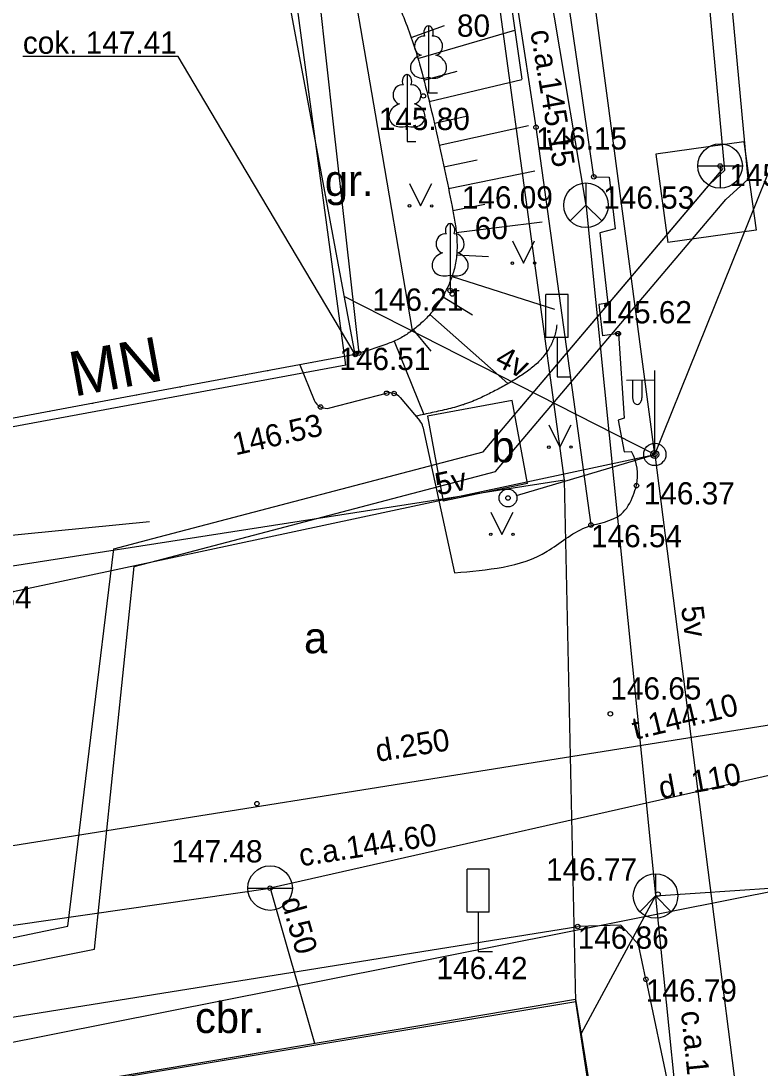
# Model space of a CAD drawing. Extents: x 728492 to 729038, y 272968 to 273171.
# Drawn here: x 728651.84 to 728668.45, y 273065.2 to 273088.71 of the extents above; entities that cross this region are included whole.
import ezdxf

# ---------------------------------------------------------------- set-up
doc = ezdxf.new("R2010")
doc.units = 0
for name, color, linetype in [('APGR_SARK_####_####_#', 7, 'Continuous'), ('APGS_ELEM_####_####_#', 7, 'Continuous'), ('BUVE_BDET_####_####_#', 7, 'Continuous'), ('BUVE_BDET_####_TKST_#', 7, 'Continuous'), ('BUVE_EKAS_####_####_#', 7, 'Continuous'), ('BUVE_EKAS_RAKS_TKST_#', 7, 'Continuous'), ('CELI_CAPM_####_####_#', 7, 'Continuous'), ('CELI_CMAL_####_####_#', 7, 'Continuous'), ('CELI_CSEG_####_TKST_#', 7, 'Continuous'), ('CELI_ELEM_####_####_#', 7, 'Continuous'), ('ELEK_ELEM_####_####_#', 7, 'Continuous'), ('ELEK_STUT_####_####_#', 7, 'Continuous'), ('ELEK_VADP_ZSPR_####_#', 7, 'Continuous'), ('ELEK_VADV_ZSPR_####_#', 7, 'Continuous'), ('ELEK_VADV_ZSPR_TKST_#', 7, 'Continuous'), ('Level 18', 7, 'Continuous'), ('RELJ_AATZ_####_TKST_#', 7, 'Continuous'), ('RELJ_ELEM_####_####_#', 7, 'Continuous'), ('RELJ_NOGA_####_####_#', 7, 'Continuous'), ('RELJ_NOGL_####_####_#', 7, 'Continuous'), ('ROBZ_UZMR_####_####_#', 7, 'Continuous'), ('SAKK_ELEM_####_####_#', 7, 'Continuous'), ('SAKK_ELEM_####_TKST_#', 7, 'Continuous'), ('SAKK_KKAN_####_####_#', 7, 'Continuous'), ('SAKK_KKAN_####_TKST_#', 7, 'Continuous'), ('SAKT_VADV_PKAB_####_#', 7, 'Continuous'), ('SILT_ELEM_####_####_#', 7, 'Continuous'), ('SILT_ELEM_####_TKST_#', 7, 'Continuous'), ('SILT_VADP_UDEN_####_#', 7, 'Continuous'), ('SILT_VADP_UDEN_TKAM_#', 7, 'Continuous'), ('SKAN_VADP_PAST_####_#', 7, 'Continuous'), ('SKAN_VADP_PAST_TKST_#', 7, 'Continuous'), ('TERT_DIAM_####_TKST_#', 7, 'Continuous'), ('TERT_ELEM_####_####_#', 7, 'Continuous'), ('UDTK_ELEM_####_####_#', 7, 'Continuous'), ('UDTK_ELEM_####_TKST_#', 7, 'Continuous'), ('UDTK_VADP_UDEN_####_#', 7, 'Continuous'), ('UDTK_VADP_UDEN_TKST_#', 7, 'Continuous')]:
    doc.layers.add(name, color=color, linetype=linetype)

msp = doc.modelspace()

# ---------------------------------------------------------------- linework, layer by layer
at = {"layer": 'APGR_SARK_####_####_#'}
for points in [[(728659.143, 273080.982), (728656.032, 273103.923)], [(728659.143, 273080.982), (728541.407, 273059.185)]]:
    msp.add_lwpolyline(points, dxfattribs=at)
at = {"layer": 'APGS_ELEM_####_####_#'}
for p, q in [((728666.081, 273080.646), (728665.446, 273080.641)), ((728665.581, 273080.642), (728665.581, 273080.25)), ((728665.791, 273080.644), (728665.791, 273080.25)), ((728666.081, 273078.979), (728666.081, 273080.862))]:
    msp.add_line(p, q, dxfattribs=at)
msp.add_circle((728666.081, 273078.979), 0.09, dxfattribs=at)
msp.add_ellipse((728665.686, 273080.25), major_axis=(0, 0.151), ratio=0.695971, start_param=1.570796, end_param=4.712389, dxfattribs=at)
at = {"layer": 'BUVE_BDET_####_####_#'}
for p, q in [((728662.877, 273080.19), (728660.973, 273079.837)), ((728663.223, 273078.324), (728662.877, 273080.19)), ((728660.973, 273079.837), (728661.327, 273077.929)), ((728663.223, 273078.324), (728661.327, 273077.929))]:
    msp.add_line(p, q, dxfattribs=at)
for points in [[(728656.596, 273085.856), (728655.376, 273087.909), (728651.883, 273087.909)], [(728659.346, 273081.225), (728656.596, 273085.856)]]:
    msp.add_lwpolyline(points, dxfattribs=at)
at = {"layer": 'BUVE_EKAS_####_####_#'}
for p, q in [((728658.403, 273086.287), (728657.68, 273090.168)), ((728659.346, 273081.225), (728658.403, 273086.287)), ((728659.346, 273081.225), (728654.187, 273080.264)), ((728654.187, 273080.264), (728650.273, 273079.535)), ((728648.966, 273064.165), (728664.302, 273066.748)), ((728664.302, 273066.748), (728666.605, 273052.429)), ((728653.698, 273064.962), (728657.04, 273065.525))]:
    msp.add_line(p, q, dxfattribs=at)
at = {"layer": 'CELI_CAPM_####_####_#'}
msp.add_line((728648.342, 273065.816), (728664.349, 273068.383), dxfattribs=at)
msp.add_lwpolyline([(728665.881, 273067.196), (728665.715, 273067.977), (728665.518, 273068.193), (728665.321, 273068.409), (728664.349, 273068.383)], dxfattribs=at)
at = {"layer": 'CELI_CMAL_####_####_#'}
for p, q in [((728664.35, 273087.706), (728662.947, 273097.421)), ((728658.304, 273091.34), (728658.856, 273086.395)), ((728659.806, 273086.622), (728658.999, 273091.36)), ((728664.71, 273085.211), (728664.35, 273087.706)), ((728660.634, 273081.763), (728659.806, 273086.622)), ((728658.856, 273086.395), (728659.429, 273081.252)), ((728664.71, 273085.211), (728665.059, 273085.2)), ((728665.059, 273085.2), (728665.193, 273084.045)), ((728665.193, 273084.045), (728664.844, 273083.956)), ((728664.844, 273083.956), (728665.024, 273082.374)), ((728665.024, 273082.374), (728664.825, 273082.347)), ((728664.825, 273082.347), (728664.907, 273081.643)), ((728665.263, 273081.691), (728664.907, 273081.643)), ((728665.263, 273081.691), (728665.396, 273079.79)), ((728658.105, 273080.994), (728658.428, 273080.2)), ((728658.781, 273080.023), (728660.056, 273080.353)), ((728660.361, 273080.256), (728660.804, 273079.732)), ((728665.396, 273079.79), (728665.255, 273079.747)), ((728665.255, 273079.747), (728665.395, 273079.037)), ((728660.868, 273079.602), (728661.581, 273076.324)), ((728665.395, 273079.037), (728665.561, 273079.043)), ((728665.881, 273067.196), (728666.991, 273061.921))]:
    msp.add_line(p, q, dxfattribs=at)
for points in [[(728663.412, 273086.324), (728661.767, 273097.047)], [(728664.648, 273077.396), (728663.412, 273086.324)]]:
    msp.add_lwpolyline(points, dxfattribs=at)
for centre, radius, start, end in [((728658.706, 273080.313), 0.3, 202.1374, 284.5077), ((728660.132, 273080.062), 0.3, 40.2151, 104.5077), ((728660.575, 273079.538), 0.3, 12.2733, 40.2151), ((728664.579, 273078.515), 1.115, 347.8099, 28.2822)]:
    msp.add_arc(centre, radius, start, end, dxfattribs=at)
msp.add_spline([(728661.581, 273076.324), (728663.664, 273076.805), (728664.527, 273077.338), (728665.324, 273077.639), (728665.598, 273078.061), (728665.669, 273078.279)], degree=3, dxfattribs=at)
at = {"layer": 'CELI_ELEM_####_####_#'}
for p, q in [((728664.136, 273082.572), (728663.636, 273082.572)), ((728663.636, 273081.603), (728663.636, 273082.572)), ((728664.136, 273081.603), (728664.136, 273082.572)), ((728664.136, 273081.603), (728663.636, 273081.603)), ((728663.89, 273081.603), (728663.89, 273080.725)), ((728663.89, 273080.725), (728664.205, 273080.725)), ((728662.362, 273069.669), (728661.862, 273069.669)), ((728661.862, 273068.7), (728661.862, 273069.669)), ((728662.362, 273068.7), (728662.362, 273069.669)), ((728662.362, 273068.7), (728661.862, 273068.7)), ((728662.116, 273068.7), (728662.116, 273067.822)), ((728662.116, 273067.822), (728662.431, 273067.822))]:
    msp.add_line(p, q, dxfattribs=at)
at = {"layer": 'ELEK_ELEM_####_####_#'}
msp.add_circle((728666.081, 273078.979), 0.25, dxfattribs=at)
at = {"layer": 'ELEK_STUT_####_####_#'}
msp.add_line((728662.975, 273078.058), (728666.081, 273078.979), dxfattribs=at)
msp.add_circle((728662.783, 273078.002), 0.2, dxfattribs=at)
at = {"layer": 'ELEK_VADP_ZSPR_####_#'}
msp.add_lwpolyline([(728654.729, 273077.464), (728649.047, 273076.903)], dxfattribs=at)
at = {"layer": 'ELEK_VADV_ZSPR_####_#'}
for p, q in [((728666.081, 273078.979), (728675.06, 273101.261)), ((728666.081, 273078.979), (728663.771, 273096.342)), ((728666.081, 273078.979), (728659.104, 273082.525)), ((728617.923, 273068.708), (728666.081, 273078.979)), ((728666.081, 273078.979), (728668.226, 273062.202))]:
    msp.add_line(p, q, dxfattribs=at)
at = {"layer": 'Level 18'}
msp.add_line((728661.717, 273097.031), (728663.093, 273087.406), dxfattribs=at)
at = {"layer": 'RELJ_ELEM_####_####_#'}
for centre in [(728660.883, 273087.027), (728663.412, 273086.324), (728667.549, 273085.455), (728664.71, 273085.211), (728661.482, 273082.66), (728661.531, 273082.581), (728665.247, 273081.689), (728665.263, 273081.691), (728659.352, 273081.222), (728659.366, 273081.244), (728659.429, 273081.252), (728660.056, 273080.353), (728660.223, 273080.348), (728658.571, 273080.045), (728658.571, 273080.045), (728666.081, 273078.979), (728665.669, 273078.279), (728662.783, 273078.002), (728664.648, 273077.396), (728665.083, 273073.155), (728657.142, 273071.139), (728657.437, 273069.243), (728666.153, 273069.107), (728664.349, 273068.383), (728665.881, 273067.196)]:
    msp.add_circle(centre, 0.05, dxfattribs=at)
at = {"layer": 'RELJ_NOGA_####_####_#'}
for p, q in [((728660.607, 273088.342), (728661.357, 273088.611)), ((728660.76, 273087.866), (728662.936, 273088.505)), ((728660.892, 273087.384), (728661.644, 273087.585)), ((728661.014, 273086.899), (728663.094, 273087.394)), ((728661.129, 273086.413), (728661.881, 273086.584)), ((728661.238, 273085.925), (728663.242, 273086.36)), ((728661.343, 273085.436), (728662.089, 273085.594)), ((728661.445, 273084.946), (728663.387, 273085.345)), ((728661.543, 273084.456), (728662.266, 273084.6)), ((728661.621, 273083.962), (728663.551, 273084.2)), ((728661.629, 273083.463), (728662.344, 273083.424)), ((728661.525, 273082.976), (728663.831, 273082.242)), ((728661.314, 273082.523), (728661.985, 273082.11)), ((728661.023, 273082.118), (728662.78, 273080.568)), ((728660.655, 273081.78), (728661.047, 273081.296)), ((728659.756, 273081.358), (728659.757, 273081.355)), ((728660.228, 273081.524), (728660.891, 273079.877)), ((728658.854, 273081.133), (728658.855, 273081.13)), ((728657.871, 273080.95), (728657.872, 273080.947)), ((728658.363, 273081.042), (728658.365, 273081.032)), ((728656.397, 273080.676), (728656.399, 273080.666)), ((728656.888, 273080.767), (728656.889, 273080.764)), ((728657.38, 273080.859), (728657.382, 273080.849)), ((728655.414, 273080.493), (728655.415, 273080.483)), ((728655.905, 273080.584), (728655.906, 273080.581)), ((728653.939, 273080.218), (728653.94, 273080.215)), ((728654.431, 273080.309), (728654.432, 273080.3)), ((728654.922, 273080.401), (728654.923, 273080.398)), ((728652.464, 273079.943), (728652.466, 273079.933)), ((728652.956, 273080.035), (728652.956, 273080.032)), ((728653.447, 273080.126), (728653.449, 273080.116)), ((728651.973, 273079.852), (728651.973, 273079.849))]:
    msp.add_line(p, q, dxfattribs=at)
for points in [[(728659.183, 273096.227), (728659.291, 273095.231), (728659.325, 273094.399), (728659.298, 273093.563), (728659.283, 273092.727), (728659.302, 273092.311), (728659.322, 273092.104), (728659.351, 273091.897), (728659.621, 273090.834), (728660.016, 273089.807), (728660.44, 273088.787), (728660.632, 273088.27), (728660.796, 273087.745), (728661.008, 273086.925), (728661.012, 273086.909)], [(728661.012, 273086.909), (728661.2, 273086.1), (728661.378, 273085.273), (728661.545, 273084.445), (728661.602, 273084.114), (728661.635, 273083.778), (728661.628, 273083.442), (728661.605, 273083.275), (728661.567, 273083.109), (728661.472, 273082.837), (728661.344, 273082.573), (728661.002, 273082.094), (728660.792, 273081.891), (728660.565, 273081.713), (728660.322, 273081.566), (728660.061, 273081.457), (728659.346, 273081.225)]]:
    msp.add_spline(points, degree=3, dxfattribs=at)
at = {"layer": 'RELJ_NOGL_####_####_#'}
msp.add_spline([(728663.881, 273081.892), (728663.856, 273081.748), (728663.822, 273081.617), (728663.799, 273081.553), (728663.773, 273081.49), (728663.743, 273081.428), (728663.709, 273081.368), (728663.632, 273081.251), (728663.542, 273081.137), (728663.442, 273081.03), (728663.334, 273080.935), (728663.219, 273080.849), (728663.092, 273080.762), (728662.964, 273080.677), (728662.833, 273080.596), (728662.7, 273080.52), (728662.426, 273080.377), (728662.156, 273080.245), (728661.982, 273080.171), (728661.806, 273080.104), (728661.716, 273080.075), (728661.626, 273080.048), (728661.443, 273080), (728661.261, 273079.959), (728661.079, 273079.919), (728660.715, 273079.837)], degree=3, dxfattribs=at)
at = {"layer": 'ROBZ_UZMR_####_####_#'}
for p, q in [((728664.052, 273078.4), (728661.768, 273095.074)), ((728664.052, 273078.4), (728634.713, 273073.836)), ((728664.304, 273066.697), (728664.052, 273078.4)), ((728648.952, 273064.144), (728664.304, 273066.697)), ((728666.873, 273050.088), (728664.304, 273066.697))]:
    msp.add_line(p, q, dxfattribs=at)
at = {"layer": 'SAKK_ELEM_####_####_#'}
for p, q in [((728664.534, 273084.574), (728664.888, 273084.22)), ((728666.097, 273069.067), (728666.451, 273068.713))]:
    msp.add_line(p, q, dxfattribs=at)
for points in [[(728664.534, 273085.074), (728664.534, 273084.574), (728664.18, 273084.22)], [(728666.097, 273069.567), (728666.097, 273069.067), (728665.743, 273068.713)]]:
    msp.add_lwpolyline(points, dxfattribs=at)
for centre in [(728664.534, 273084.574), (728666.097, 273069.067)]:
    msp.add_circle(centre, 0.5, dxfattribs=at)
at = {"layer": 'SAKK_KKAN_####_####_#'}
msp.add_line((728666.097, 273069.067), (728664.426, 273065.977), dxfattribs=at)
for points in [[(728662.399, 273097.247), (728664.534, 273084.574)], [(728664.534, 273084.574), (728664.542, 273084.535), (728666.095, 273069.085), (728666.099, 273069.049), (728666.82, 273061.882)], [(728666.097, 273069.067), (728672.335, 273069.49), (728677.209, 273069.82)]]:
    msp.add_lwpolyline(points, dxfattribs=at)
at = {"layer": 'SAKT_VADV_PKAB_####_#'}
msp.add_line((728635.134, 273062.502), (728677.472, 273070.914), dxfattribs=at)
at = {"layer": 'SILT_ELEM_####_####_#'}
for p, q in [((728667.049, 273085.455), (728667.549, 273085.455)), ((728667.549, 273085.455), (728668.049, 273085.455)), ((728667.549, 273085.455), (728667.549, 273084.955))]:
    msp.add_line(p, q, dxfattribs=at)
msp.add_circle((728667.549, 273085.455), 0.5, dxfattribs=at)
at = {"layer": 'SILT_VADP_UDEN_####_#'}
for p, q in [((728668.083, 273085.995), (728668.358, 273084.014)), ((728662.225, 273079.037), (728667.619, 273085.4))]:
    msp.add_line(p, q, dxfattribs=at)
for points in [[(728667.373, 273088.428), (728666.865, 273093.904)], [(728667.865, 273088.545), (728667.363, 273093.95)], [(728654.802, 273077.089), (728662.225, 273079.037), (728667.319, 273085.05), (728667.658, 273085.361), (728667.373, 273088.428)], [(728654.897, 273076.597), (728662.505, 273078.593), (728667.68, 273084.703), (728668.179, 273085.16), (728667.865, 273088.545)], [(728554.662, 273032.952), (728554.113, 273035.473), (728554.267, 273035.774), (728581.419, 273054.878), (728582.018, 273055.208), (728610.89, 273060.328), (728630.183, 273063.782), (728638.039, 273065.289), (728652.893, 273068.386), (728653.925, 273076.859), (728654.802, 273077.089)], [(728555.193, 273032.922), (728554.64, 273035.405), (728554.656, 273035.436), (728581.684, 273054.453), (728582.187, 273054.73), (728610.978, 273059.835), (728630.274, 273063.29), (728638.144, 273064.8), (728653.493, 273067.873), (728654.384, 273076.462), (728654.897, 273076.597)]]:
    msp.add_lwpolyline(points, dxfattribs=at)
at = {"layer": 'SILT_VADP_UDEN_TKAM_#'}
for p, q in [((728668.083, 273085.995), (728666.102, 273085.72)), ((728668.083, 273085.995), (728668.358, 273084.014)), ((728666.102, 273085.72), (728666.377, 273083.739)), ((728668.358, 273084.014), (728666.377, 273083.739))]:
    msp.add_line(p, q, dxfattribs=at)
at = {"layer": 'SKAN_VADP_PAST_####_#'}
msp.add_lwpolyline([(728616.534, 273064.605), (728669.124, 273072.987)], dxfattribs=at)
at = {"layer": 'TERT_ELEM_####_####_#'}
for p, q in [((728660.997, 273087.447), (728660.997, 273087.1)), ((728660.997, 273087.1), (728661.197, 273087.1)), ((728660.514, 273086.352), (728660.514, 273086.005)), ((728660.514, 273086.005), (728660.714, 273086.005)), ((728660.57, 273085.06), (728660.82, 273084.56)), ((728660.82, 273084.56), (728661.07, 273085.06)), ((728662.881, 273083.774), (728663.131, 273083.274)), ((728663.131, 273083.274), (728663.381, 273083.774)), ((728661.482, 273083.007), (728661.482, 273082.66)), ((728661.482, 273082.66), (728661.682, 273082.66)), ((728663.701, 273079.644), (728663.951, 273079.144)), ((728663.951, 273079.144), (728664.201, 273079.644)), ((728662.396, 273077.685), (728662.646, 273077.185)), ((728662.646, 273077.185), (728662.896, 273077.685))]:
    msp.add_line(p, q, dxfattribs=at)
for points in [[(728660.997, 273088.6), (728660.997, 273087.447)], [(728661.087, 273088.368), (728661.086, 273088.369)], [(728660.514, 273087.505), (728660.514, 273086.352)], [(728660.604, 273087.273), (728660.603, 273087.274)], [(728661.482, 273084.16), (728661.482, 273083.007)], [(728661.572, 273083.928), (728661.571, 273083.929)]]:
    msp.add_lwpolyline(points, dxfattribs=at)
for centre, radius in [((728660.569, 273084.559), 0.028), ((728661.069, 273084.559), 0.0263), ((728662.881, 273083.274), 0.028), ((728663.381, 273083.274), 0.0263), ((728663.701, 273079.143), 0.028), ((728664.201, 273079.143), 0.0263), ((728662.396, 273077.184), 0.028), ((728662.896, 273077.184), 0.0263)]:
    msp.add_circle(centre, radius, dxfattribs=at)
for centre, major_axis, ratio, start_param, end_param in [((728660.997, 273088.45), (0, -0.15), 0.707107, 3.14537, 5.287485), ((728660.997, 273088.45), (0, -0.15), 0.707107, 0.995701, 3.137816), ((728660.869, 273088.155), (-0.039, -0.212), 0.861323, 3.141593, 6.283185), ((728661.125, 273088.155), (0.039, -0.212), 0.861323, 0, 3.141593), ((728660.907, 273087.693), (0.307, 0.095), 0.814445, 1.570796, 4.752015), ((728661.087, 273087.693), (-0.307, 0.095), 0.814445, 1.531171, 4.712389), ((728660.514, 273087.355), (0, -0.15), 0.707107, 3.14537, 5.287485), ((728660.514, 273087.355), (0, -0.15), 0.707107, 0.995701, 3.137816), ((728660.386, 273087.06), (-0.039, -0.212), 0.861323, 3.141593, 6.283185), ((728660.642, 273087.06), (0.039, -0.212), 0.861323, 0, 3.141593), ((728660.424, 273086.598), (0.307, 0.095), 0.814445, 1.570796, 4.752015), ((728660.604, 273086.598), (-0.307, 0.095), 0.814445, 1.531171, 4.712389), ((728661.354, 273083.715), (-0.039, -0.212), 0.861323, 3.141593, 6.283185), ((728661.482, 273084.01), (0, -0.15), 0.707107, 3.14537, 5.287485), ((728661.482, 273084.01), (0, -0.15), 0.707107, 0.995701, 3.137816), ((728661.61, 273083.715), (0.039, -0.212), 0.861323, 0, 3.141593), ((728661.392, 273083.253), (0.307, 0.095), 0.814445, 1.570796, 4.752015), ((728661.572, 273083.253), (-0.307, 0.095), 0.814445, 1.531171, 4.712389)]:
    msp.add_ellipse(centre, major_axis=major_axis, ratio=ratio, start_param=start_param, end_param=end_param, dxfattribs=at)
at = {"layer": 'UDTK_ELEM_####_####_#'}
msp.add_line((728656.938, 273069.243), (728657.938, 273069.243), dxfattribs=at)
msp.add_circle((728657.438, 273069.243), 0.5, dxfattribs=at)
at = {"layer": 'UDTK_VADP_UDEN_####_#'}
for p, q in [((728673.219, 273072.807), (728657.437, 273069.243)), ((728657.437, 273069.243), (728658.435, 273065.76))]:
    msp.add_line(p, q, dxfattribs=at)
msp.add_lwpolyline([(728536.753, 273051.73), (728562.041, 273055.954), (728585.763, 273058.374), (728605.397, 273061.619), (728606.945, 273061.767), (728607.469, 273061.897), (728613.688, 273063.022), (728614.11, 273063.005), (728657.437, 273069.243)], dxfattribs=at)

# ---------------------------------------------------------------- texts
at = {"layer": 'BUVE_BDET_####_TKST_#'}
msp.add_text('cok. 147.41', height=0.49999, dxfattribs=at).set_placement((728651.883, 273087.974))
at = {"layer": 'BUVE_EKAS_RAKS_TKST_#'}
msp.add_text('MN', height=1, rotation=10.404, dxfattribs=at).set_placement((728653.03, 273080.275))
at = {"layer": 'CELI_CSEG_####_TKST_#'}
for s, p in [('gr.', (728658.668, 273084.779)), ('b', (728662.412, 273078.803)), ('a', (728658.2, 273074.516)), ('cbr.', (728655.751, 273065.99))]:
    msp.add_text(s, height=0.7, dxfattribs=at).set_placement(p)
at = {"layer": 'ELEK_VADV_ZSPR_TKST_#'}
for s, rotation, p in [('4v', 333.058, (728662.46, 273080.994)), ('5v', 11.7683, (728661.2, 273078.056)), ('5v', 277.2851, (728666.67, 273075.553))]:
    msp.add_text(s, height=0.5, rotation=rotation, dxfattribs=at).set_placement(p)
at = {"layer": 'RELJ_AATZ_####_TKST_#'}
for s, p in [(' 145.80', (728659.694, 273086.261)), ('146.15', (728663.412, 273085.824)), ('146.53', (728664.923, 273084.496)), (' 146.21', (728659.549, 273082.205)), (' 145.62', (728664.686, 273081.922)), (' 146.51', (728658.807, 273080.873)), ('146.37', (728665.833, 273077.856)), ('146.54', (728664.648, 273076.896)), ('147.34', (728650.036, 273075.521)), ('146.65', (728665.083, 273073.476)), ('146.86', (728664.349, 273067.883)), (' 146.42', (728660.992, 273067.199)), ('146.79', (728665.881, 273066.696))]:
    msp.add_text(s, height=0.5, dxfattribs=at).set_placement(p)
msp.add_text(' 146.53', height=0.5, rotation=12.9565, dxfattribs=at).set_placement((728656.478, 273078.914))
at = {"layer": 'SAKK_ELEM_####_TKST_#'}
for s, p in [(' 146.09', (728661.56, 273084.5)), (' 146.77', (728663.452, 273069.414))]:
    msp.add_text(s, height=0.5, dxfattribs=at).set_placement(p)
at = {"layer": 'SAKK_KKAN_####_TKST_#'}
for s, rotation, p in [('c.a.145.15', 279.565, (728663.281, 273088.477)), ('c.a.145.85', 275.749, (728666.668, 273066.47))]:
    msp.add_text(s, height=0.5, rotation=rotation, dxfattribs=at).set_placement(p)
at = {"layer": 'SILT_ELEM_####_TKST_#'}
msp.add_text('145.87', height=0.5, dxfattribs=at).set_placement((728667.756, 273085.002))
at = {"layer": 'SKAN_VADP_PAST_TKST_#'}
for s, rotation, p in [('t.144.10', 13.5945, (728665.641, 273072.57)), ('d.250', 9.103, (728659.848, 273072.076))]:
    msp.add_text(s, height=0.5, rotation=rotation, dxfattribs=at).set_placement(p)
at = {"layer": 'TERT_DIAM_####_TKST_#'}
for s, p in [('80', (728661.636, 273088.356)), ('60', (728662.036, 273083.811))]:
    msp.add_text(s, height=0.5, dxfattribs=at).set_placement(p)
at = {"layer": 'UDTK_ELEM_####_TKST_#'}
msp.add_text('147.48', height=0.5, dxfattribs=at).set_placement((728655.223, 273069.82))
at = {"layer": 'UDTK_VADP_UDEN_TKST_#'}
for s, rotation, p in [('d. 110', 10.1977, (728666.218, 273071.243)), ('c.a.144.60', 8.8177, (728658.125, 273069.729)), ('d.50', 285.9886, (728657.676, 273068.969))]:
    msp.add_text(s, height=0.5, rotation=rotation, dxfattribs=at).set_placement(p)

doc.saveas('drawing.dxf')
